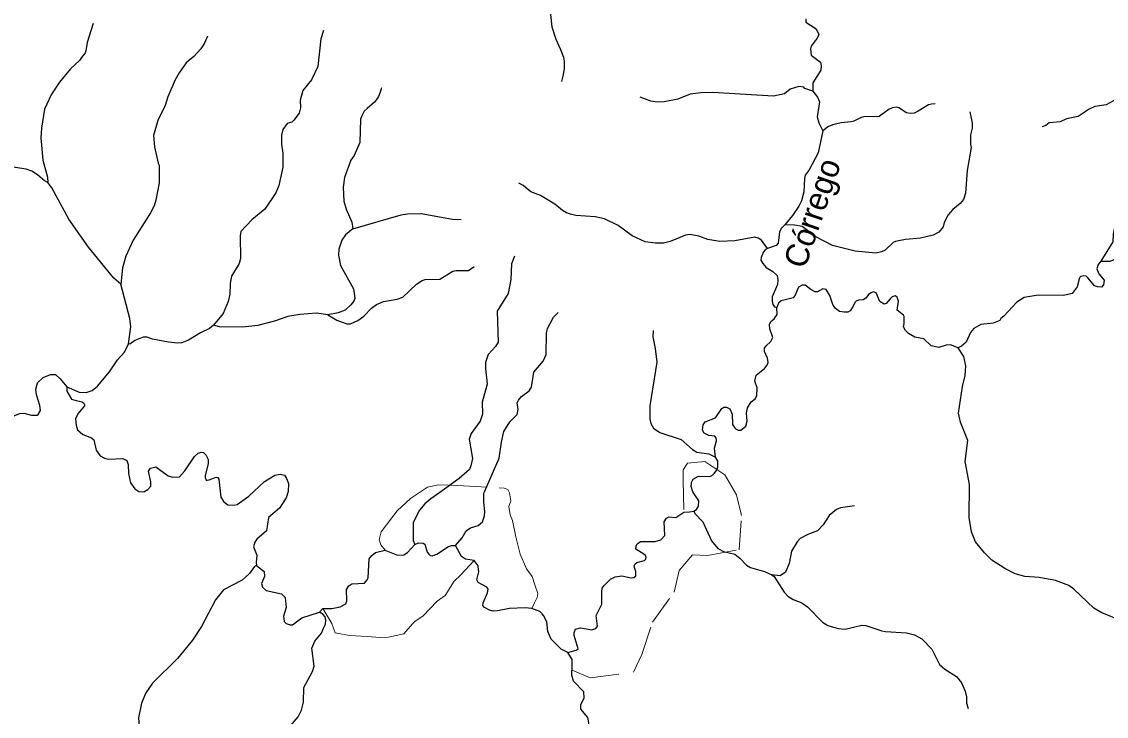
# Model space of a CAD drawing. Extents: x 320.3 to 346.3, y 7455.4 to 7483.3.
# Drawn here: x 336.328 to 340.058, y 7479.449 to 7481.838 of the extents above; entities that cross this region are included whole.
import ezdxf
from ezdxf.enums import TextEntityAlignment as Align

# ---------------------------------------------------------------- set-up
doc = ezdxf.new("R2010")
doc.units = 0
doc.header["$LTSCALE"] = 0.032
doc.linetypes.add('SHORT_DASHED', pattern=[2.7, 1.5, -1.2])
doc.layers.add('21', color=7, linetype='SHORT_DASHED', lineweight=13)
doc.layers.add('7', color=7, linetype='Continuous', lineweight=25)
doc.layers.add('61', color=7, linetype='Continuous')

msp = doc.modelspace()

# ---------------------------------------------------------------- linework, layer by layer
at = {"layer": '21'}
for points in [[(338.2208, 7479.6077), (338.2826, 7479.581), (338.4315, 7479.6011), (338.4601, 7479.6613), (338.4973, 7479.773), (338.5718, 7479.8761), (338.5889, 7479.9506), (338.6347, 7480.005), (338.6863, 7480.0022), (338.7951, 7480.0222), (338.8037, 7480.1397), (338.7865, 7480.2113), (338.7464, 7480.28), (338.6777, 7480.3259), (338.6176, 7480.3201), (338.6032, 7480.2972), (338.6032, 7480.26), (338.6056, 7480.1509)], [(337.6195, 7480.1558), (337.6651, 7480.1978), (337.7243, 7480.2377)], [(337.7243, 7480.2377), (337.7616, 7480.2452), (337.8278, 7480.2425), (337.9697, 7480.2344)], [(337.9697, 7480.2344), (337.9869, 7480.2335), (337.9994, 7480.2291), (338.0057, 7480.218)], [(338.0057, 7480.218), (338.0101, 7480.1906), (338.0038, 7480.171), (338.0083, 7480.1423), (338.0164, 7480.1225)], [(337.5777, 7480.0204), (337.5629, 7480.039), (337.558, 7480.0562), (337.5639, 7480.0837), (337.6195, 7480.1558)], [(338.0164, 7480.1225), (338.028, 7480.0663), (338.0423, 7480.0073), (338.0646, 7479.956)], [(337.8159, 7479.9135), (337.8367, 7479.9349), (337.8838, 7479.9851)], [(338.0646, 7479.956), (338.0834, 7479.9295), (338.0923, 7479.9012), (338.1032, 7479.8718), (338.1005, 7479.858)], [(337.757, 7479.8447), (337.7849, 7479.8652), (337.8159, 7479.9135)], [(337.6817, 7479.7759), (337.708, 7479.7936), (337.757, 7479.8447)], [(338.1005, 7479.858), (338.0914, 7479.8392), (338.0826, 7479.8198)], [(337.3643, 7479.8195), (337.3951, 7479.7685), (337.4068, 7479.7366)], [(337.6424, 7479.7333), (337.6714, 7479.7659), (337.6817, 7479.7759)], [(337.4068, 7479.7366), (337.4551, 7479.7266), (337.5167, 7479.7239), (337.5614, 7479.7203), (337.59, 7479.7212), (337.6424, 7479.7333)]]:
    msp.add_lwpolyline(points, dxfattribs=at)
at = {"layer": '7'}
for points in [[(338.181, 7482.0499), (338.1843, 7482.0255), (338.1824, 7482.005), (338.1498, 7481.8941), (338.1468, 7481.8625), (338.1513, 7481.8197), (338.1648, 7481.778), (338.1813, 7481.7427), (338.1908, 7481.7156), (338.1933, 7481.7017), (338.1934, 7481.676), (338.1887, 7481.651), (338.1839, 7481.632)], [(339.0241, 7481.8479), (339.0251, 7481.8366), (339.0565, 7481.8161), (339.064, 7481.807), (339.0688, 7481.7943), (339.0639, 7481.7814), (339.0429, 7481.7539), (339.0406, 7481.7446), (339.0428, 7481.7231), (339.0745, 7481.6987), (339.0772, 7481.6858), (339.0763, 7481.6715), (339.0482, 7481.6272), (339.0486, 7481.5993)], [(336.5741, 7481.8315), (336.554, 7481.766), (336.5487, 7481.7379), (336.5463, 7481.7306), (336.543, 7481.7261), (336.5342, 7481.7146), (336.5275, 7481.705), (336.4959, 7481.6761), (336.458, 7481.6303), (336.4308, 7481.589), (336.407, 7481.5371), (336.3963, 7481.472), (336.3939, 7481.4384), (336.4012, 7481.3621), (336.4173, 7481.3029), (336.4184, 7481.2852)], [(337.3657, 7481.8073), (337.3571, 7481.7787), (337.3469, 7481.6843), (337.3251, 7481.638), (337.2954, 7481.6015), (337.2863, 7481.5685), (337.2871, 7481.5417), (337.2828, 7481.5238), (337.2644, 7481.4993), (337.2569, 7481.4927), (337.2417, 7481.4874), (337.2262, 7481.467), (337.2217, 7481.4475), (337.2216, 7481.4169), (337.2264, 7481.3853), (337.2264, 7481.3379), (337.2128, 7481.2743), (337.2023, 7481.2494), (337.1644, 7481.1927), (337.1203, 7481.1564), (337.0824, 7481.1167), (337.08, 7481.1014), (337.0805, 7481.0234), (337.0759, 7481.0059), (337.0497, 7480.9626), (337.0447, 7480.9381), (337.0442, 7480.901), (337.0388, 7480.8753), (337.0217, 7480.8341), (336.9876, 7480.7949)], [(336.9675, 7481.788), (336.9574, 7481.7641), (336.944, 7481.7447), (336.9198, 7481.7178), (336.8942, 7481.6959), (336.8701, 7481.6625), (336.8556, 7481.6376), (336.8309, 7481.5795), (336.8221, 7481.5499), (336.796, 7481.4978), (336.7812, 7481.4469), (336.7847, 7481.4081), (336.7978, 7481.3509), (336.8016, 7481.3445), (336.8014, 7481.2833), (336.7893, 7481.2246), (336.7835, 7481.2043), (336.7718, 7481.1806), (336.7117, 7481.0863), (336.6863, 7481.0313), (336.6747, 7480.992), (336.669, 7480.9351)], [(339.0486, 7481.5993), (339.0216, 7481.6085), (339.0182, 7481.6126), (339.0002, 7481.6149), (338.9705, 7481.6062), (338.9511, 7481.5903), (338.9133, 7481.5818), (338.7035, 7481.595), (338.6638, 7481.5934), (338.6274, 7481.5889), (338.5845, 7481.5718), (338.538, 7481.5622), (338.5147, 7481.5612), (338.4918, 7481.565), (338.455, 7481.5789)], [(337.5652, 7481.611), (337.5613, 7481.5957), (337.5553, 7481.5812), (337.5486, 7481.5703), (337.5417, 7481.5617), (337.516, 7481.5396), (337.5064, 7481.5308), (337.4978, 7481.514), (337.4937, 7481.5023), (337.4912, 7481.4226), (337.4715, 7481.3775), (337.4603, 7481.362), (337.4389, 7481.3025), (337.4341, 7481.2692), (337.4363, 7481.2212), (337.4441, 7481.1935), (337.463, 7481.1491), (337.467, 7481.1261)], [(339.0486, 7481.5993), (339.0646, 7481.5782), (339.0716, 7481.5619), (339.0634, 7481.5113), (339.0694, 7481.4904), (339.0831, 7481.4628)], [(340.1924, 7481.5821), (340.1671, 7481.6051), (340.1494, 7481.6123), (340.1366, 7481.6112), (340.1185, 7481.5989), (340.0825, 7481.5659), (340.0571, 7481.5519), (340.0187, 7481.5458), (339.999, 7481.5369), (339.9611, 7481.5122), (339.921, 7481.5044), (339.8991, 7481.494), (339.8617, 7481.4896), (339.8499, 7481.4807), (339.8372, 7481.4767)], [(339.4691, 7481.5551), (339.4561, 7481.5543), (339.4467, 7481.552), (339.411, 7481.53), (339.3974, 7481.5232), (339.3831, 7481.5219), (339.3709, 7481.5246), (339.3446, 7481.5418), (339.3349, 7481.5437), (339.322, 7481.5419), (339.3111, 7481.5371), (339.2771, 7481.512), (339.2706, 7481.5108), (339.2373, 7481.5123), (339.2234, 7481.5102), (339.2149, 7481.508), (339.1898, 7481.4963), (339.1787, 7481.4934), (339.1459, 7481.49), (339.1203, 7481.4846), (339.102, 7481.4776), (339.0831, 7481.4628)], [(339.5886, 7481.5274), (339.5965, 7481.4902), (339.5963, 7481.4713), (339.5902, 7481.4487), (339.5902, 7481.4171), (339.593, 7481.405), (339.5796, 7481.3266), (339.5734, 7481.2479), (339.5664, 7481.227), (339.5554, 7481.2128), (339.5303, 7481.1919), (339.5141, 7481.1738), (339.5003, 7481.1473), (339.4965, 7481.1329), (339.4817, 7481.1139), (339.462, 7481.1044), (339.4185, 7481.0931), (339.3675, 7481.089), (339.3326, 7481.0822), (339.3253, 7481.079), (339.2973, 7481.0522), (339.2844, 7481.0464), (339.2652, 7481.0425), (339.1947, 7481.0484), (339.1164, 7481.0679), (339.0584, 7481.0986), (339.0117, 7481.1331), (338.9852, 7481.1384), (338.9523, 7481.1396)], [(339.0831, 7481.4628), (339.0665, 7481.3868), (339.0361, 7481.3287), (339.0223, 7481.31), (339.0201, 7481.2991), (339.018, 7481.2524), (339.01, 7481.2224), (339.0006, 7481.2036), (338.9789, 7481.1717), (338.9523, 7481.1396)], [(336.4184, 7481.2852), (336.4066, 7481.2912), (336.3833, 7481.3118), (336.3631, 7481.3235), (336.3439, 7481.3303), (336.2288, 7481.3479), (336.1977, 7481.3492), (336.0964, 7481.3629), (336.0698, 7481.3616), (336.0444, 7481.3659), (336.0271, 7481.37), (336.01, 7481.3769), (335.9771, 7481.4067)], [(340.1962, 7481.4088), (340.1873, 7481.3925), (340.1856, 7481.3812), (340.1861, 7481.3694), (340.1954, 7481.3406), (340.1917, 7481.3037), (340.1789, 7481.2826), (340.1485, 7481.2558), (340.1328, 7481.2268), (340.1191, 7481.1819), (340.0896, 7481.1486), (340.0812, 7481.1075), (340.0806, 7481.0814), (340.0385, 7481.0149)], [(336.669, 7480.9351), (336.6455, 7480.9556), (336.5581, 7481.0621), (336.4906, 7481.1594), (336.4325, 7481.2669), (336.4184, 7481.2852)], [(338.8932, 7481.0581), (338.8718, 7481.0867), (338.8605, 7481.0936), (338.849, 7481.0967), (338.7803, 7481.0847), (338.7293, 7481.0824), (338.6881, 7481.0884), (338.6569, 7481.1007), (338.6263, 7481.1061), (338.6108, 7481.1035), (338.5585, 7481.082), (338.535, 7481.0767), (338.5076, 7481.0765), (338.4723, 7481.0812), (338.4277, 7481.1018), (338.3789, 7481.1373), (338.3326, 7481.1597), (338.3001, 7481.1664), (338.2338, 7481.1709), (338.2159, 7481.1757), (338.2014, 7481.1809), (338.1884, 7481.1891), (338.1612, 7481.2102), (338.1122, 7481.2408), (338.0789, 7481.2532), (338.0523, 7481.2747), (338.0375, 7481.2828)], [(337.467, 7481.1261), (337.6336, 7481.1743), (337.6555, 7481.1768), (337.7021, 7481.1785), (337.8093, 7481.1589), (337.8396, 7481.1581)], [(338.9523, 7481.1396), (338.9408, 7481.1282), (338.9339, 7481.1151), (338.9298, 7481.0766), (338.9224, 7481.068), (338.8932, 7481.0581)], [(337.467, 7481.1261), (337.4413, 7481.1045), (337.429, 7481.0863), (337.4185, 7481.0555), (337.418, 7481.0345), (337.425, 7480.999), (337.4697, 7480.919), (337.474, 7480.8873), (337.4704, 7480.8771), (337.4606, 7480.8642), (337.441, 7480.8464), (337.4169, 7480.8366), (337.3816, 7480.83)], [(338.8932, 7481.0581), (338.8862, 7481.0551), (338.8794, 7481.046), (338.8704, 7481.0266), (338.8697, 7481.0177), (338.8762, 7481.0064), (338.8887, 7480.9924), (338.9111, 7480.9791), (338.9258, 7480.9655), (338.928, 7480.9503), (338.927, 7480.9345), (338.9083, 7480.8919), (338.9083, 7480.8763), (338.9106, 7480.865), (338.9169, 7480.8578), (338.9253, 7480.8546)], [(338.023, 7481.0318), (338.0128, 7481.005), (338.0107, 7480.9519), (338.0008, 7480.9031), (337.9635, 7480.843), (337.9664, 7480.7364), (337.9576, 7480.7207), (337.9321, 7480.6932), (337.9235, 7480.6659), (337.9226, 7480.645), (337.9286, 7480.5917), (337.9118, 7480.5291), (337.9133, 7480.4881), (337.9052, 7480.4646), (337.8735, 7480.4213), (337.8672, 7480.4022), (337.8779, 7480.3354), (337.8728, 7480.3109), (337.8678, 7480.2982), (337.8329, 7480.2666), (337.7741, 7480.2251), (337.7349, 7480.1975), (337.7142, 7480.18), (337.6963, 7480.1581), (337.6739, 7480.1161), (337.6749, 7480.054), (337.6804, 7480.0405)], [(340.0385, 7481.0149), (340.0705, 7481.0147), (340.1038, 7481.0278), (340.1242, 7481.0255), (340.1328, 7481.0197), (340.1361, 7481.0136), (340.1356, 7480.9964), (340.1275, 7480.9644), (340.1294, 7480.9476), (340.1334, 7480.9408), (340.1456, 7480.9317), (340.1684, 7480.921), (340.1848, 7480.9007), (340.2013, 7480.8866), (340.228, 7480.8847), (340.2589, 7480.8871), (340.29, 7480.8706), (340.3068, 7480.8572), (340.3099, 7480.8526), (340.3085, 7480.8403), (340.2972, 7480.8148), (340.2938, 7480.7996), (340.2953, 7480.7912)], [(337.3816, 7480.83), (337.4116, 7480.8114), (337.4459, 7480.7991), (337.4589, 7480.7988), (337.4846, 7480.8108), (337.5046, 7480.8251), (337.531, 7480.8526), (337.5483, 7480.8652), (337.5724, 7480.8755), (337.6199, 7480.8838), (337.6387, 7480.8911), (337.6864, 7480.9359), (337.7054, 7480.9477), (337.7162, 7480.9512), (337.7662, 7480.9522), (337.8106, 7480.9801), (337.8218, 7480.9826), (337.8651, 7480.9821), (337.8842, 7480.9963)], [(340.0385, 7481.0149), (340.0299, 7481.0028), (340.0253, 7480.9879), (340.0318, 7480.971), (340.0501, 7480.9489), (340.0482, 7480.9333), (340.0407, 7480.9252), (340.0275, 7480.9258), (340.0172, 7480.9297), (339.9957, 7480.9564), (339.9882, 7480.9629), (339.9806, 7480.9643), (339.9703, 7480.962), (339.9651, 7480.9568), (339.9579, 7480.9264), (339.9402, 7480.9034), (339.9101, 7480.8969), (339.8229, 7480.8978), (339.7758, 7480.8891), (339.7497, 7480.8738), (339.7051, 7480.8248), (339.6946, 7480.817), (339.6916, 7480.8099), (339.669, 7480.8009), (339.6261, 7480.7961), (339.6016, 7480.7833), (339.5911, 7480.7688), (339.5759, 7480.7358), (339.5597, 7480.7216), (339.5479, 7480.7169)], [(336.6959, 7480.7296), (336.7034, 7480.7889), (336.7002, 7480.8178), (336.669, 7480.9351)], [(339.5479, 7480.7169), (339.5215, 7480.7269), (339.5076, 7480.7258), (339.4814, 7480.7178), (339.4557, 7480.7229), (339.4298, 7480.7471), (339.399, 7480.7532), (339.3774, 7480.7652), (339.3671, 7480.7757), (339.3603, 7480.7882), (339.3632, 7480.8003), (339.3626, 7480.8238), (339.3599, 7480.829), (339.3382, 7480.8459), (339.3429, 7480.8768), (339.3383, 7480.8901), (339.3319, 7480.8951), (339.3214, 7480.8919), (339.3145, 7480.8848), (339.3008, 7480.8685), (339.2941, 7480.867), (339.2793, 7480.8761), (339.266, 7480.9057), (339.2575, 7480.9094), (339.2491, 7480.9058), (339.2403, 7480.8996), (339.231, 7480.8868), (339.2215, 7480.8816), (339.2061, 7480.8808), (339.1981, 7480.8768), (339.1931, 7480.8721), (339.1873, 7480.8598), (339.1772, 7480.8431), (339.1689, 7480.8386), (339.1562, 7480.8386), (339.1404, 7480.8413), (339.1263, 7480.8516), (339.1175, 7480.865), (339.1069, 7480.8965), (339.094, 7480.9171), (339.0825, 7480.9189), (339.0642, 7480.9092), (339.0567, 7480.9093), (339.042, 7480.9165), (339.0226, 7480.932), (339.0118, 7480.9315), (338.9988, 7480.9251), (338.9884, 7480.8975), (338.9809, 7480.8881), (338.9392, 7480.8776), (338.9309, 7480.8702), (338.9253, 7480.8546)], [(337.3816, 7480.83), (337.3423, 7480.8357), (337.2844, 7480.8311), (337.2432, 7480.8236), (337.1975, 7480.808), (337.1399, 7480.7936), (337.0881, 7480.7872), (337.0084, 7480.7888), (336.9876, 7480.7949)], [(337.8199, 7480.0361), (337.8431, 7480.0627), (337.8562, 7480.0872), (337.8718, 7480.0972), (337.8978, 7480.1049), (337.9126, 7480.1184), (337.9197, 7480.1384), (337.9213, 7480.1531), (337.9169, 7480.1862), (337.9173, 7480.2163), (337.9194, 7480.221), (337.9705, 7480.3375), (337.9777, 7480.3925), (337.9866, 7480.4289), (338.0072, 7480.4623), (338.0318, 7480.4868), (338.0358, 7480.5044), (338.0326, 7480.5275), (338.0367, 7480.536), (338.0465, 7480.5487), (338.0733, 7480.5688), (338.0811, 7480.581), (338.0895, 7480.6323), (338.121, 7480.6705), (338.1315, 7480.6934), (338.1324, 7480.7667), (338.1362, 7480.7832), (338.1566, 7480.8215), (338.1728, 7480.838)], [(338.7135, 7480.3401), (338.7108, 7480.3716), (338.7175, 7480.3969), (338.7164, 7480.4065), (338.7122, 7480.4128), (338.6907, 7480.4151), (338.6745, 7480.4227), (338.6698, 7480.4333), (338.6715, 7480.4518), (338.6781, 7480.4615), (338.7138, 7480.4758), (338.7358, 7480.5077), (338.7429, 7480.5122), (338.7523, 7480.5128), (338.7631, 7480.5061), (338.7709, 7480.4888), (338.7728, 7480.4529), (338.7815, 7480.4394), (338.7922, 7480.4336), (338.8015, 7480.4327), (338.8183, 7480.4474), (338.8229, 7480.4641), (338.821, 7480.4933), (338.8241, 7480.51), (338.8366, 7480.5307), (338.8514, 7480.5426), (338.8556, 7480.5525), (338.8573, 7480.5784), (338.8488, 7480.6019), (338.8536, 7480.6222), (338.882, 7480.6456), (338.8908, 7480.656), (338.8945, 7480.6665), (338.8927, 7480.6804), (338.8828, 7480.7033), (338.8828, 7480.7153), (338.8877, 7480.7236), (338.9044, 7480.7385), (338.9108, 7480.7517), (338.9002, 7480.7814), (338.8999, 7480.7972), (338.9043, 7480.8066), (338.916, 7480.8161), (338.9264, 7480.8314), (338.9253, 7480.8546)], [(336.9876, 7480.7949), (336.9737, 7480.7834), (336.9428, 7480.7683), (336.9025, 7480.743), (336.8786, 7480.734), (336.8637, 7480.7319), (336.8327, 7480.7354), (336.7784, 7480.7459), (336.7598, 7480.7526), (336.7457, 7480.7525), (336.717, 7480.7419), (336.7008, 7480.7295), (336.6959, 7480.7296)], [(338.4993, 7480.7759), (338.498, 7480.7542), (338.507, 7480.7136), (338.5119, 7480.6668), (338.488, 7480.5171), (338.488, 7480.4716), (338.4918, 7480.4559), (338.501, 7480.4403), (338.5223, 7480.4252), (338.5957, 7480.4008), (338.6349, 7480.3665), (338.6502, 7480.3574), (338.6911, 7480.3517), (338.7135, 7480.3401)], [(336.4832, 7480.5824), (336.5263, 7480.5635), (336.5506, 7480.5625), (336.5711, 7480.5697), (336.5894, 7480.5844), (336.6302, 7480.634), (336.6584, 7480.6746), (336.6815, 7480.7012), (336.6959, 7480.7296)], [(340.1098, 7479.7778), (340.0427, 7479.8052), (340.0145, 7479.8209), (339.9455, 7479.887), (339.9286, 7479.8988), (339.8826, 7479.9164), (339.8267, 7479.927), (339.7774, 7479.9301), (339.7446, 7479.939), (339.709, 7479.9576), (339.6637, 7479.9866), (339.639, 7480.011), (339.6077, 7480.0487), (339.5944, 7480.0837), (339.5859, 7480.1327), (339.5868, 7480.2466), (339.5724, 7480.326), (339.5819, 7480.3972), (339.5562, 7480.4606), (339.5493, 7480.4914), (339.5628, 7480.5829), (339.5724, 7480.6207), (339.5751, 7480.655), (339.5683, 7480.6869), (339.5479, 7480.7169)], [(336.1919, 7480.3977), (336.2141, 7480.4039), (336.2471, 7480.4002), (336.2637, 7480.4048), (336.271, 7480.4278), (336.2712, 7480.4533), (336.2831, 7480.4721), (336.3073, 7480.4844), (336.3226, 7480.4905), (336.3354, 7480.4917), (336.3621, 7480.4847), (336.3817, 7480.4843), (336.3856, 7480.4867), (336.3932, 7480.5006), (336.3906, 7480.5184), (336.3789, 7480.5547), (336.3773, 7480.5741), (336.3832, 7480.5964), (336.4028, 7480.6139), (336.4276, 7480.6247), (336.4451, 7480.6242), (336.4612, 7480.6102), (336.4832, 7480.5824)], [(336.4832, 7480.5824), (336.484, 7480.5677), (336.5002, 7480.5404), (336.5156, 7480.535), (336.5368, 7480.5312), (336.5425, 7480.526), (336.5445, 7480.5214), (336.5445, 7480.5174), (336.5211, 7480.4895), (336.514, 7480.4727), (336.5156, 7480.4499), (336.5209, 7480.4348), (336.5384, 7480.4181), (336.5687, 7480.4067), (336.5765, 7480.4002), (336.585, 7480.3649), (336.5988, 7480.3449), (336.6127, 7480.3371), (336.6273, 7480.3336), (336.6765, 7480.3363), (336.6894, 7480.3291), (336.6951, 7480.3152), (336.6956, 7480.2842), (336.703, 7480.2521), (336.7169, 7480.2317), (336.7317, 7480.2222), (336.7484, 7480.2213), (336.7625, 7480.2293), (336.7721, 7480.2405), (336.772, 7480.2558), (336.7647, 7480.2919), (336.7715, 7480.3025), (336.7891, 7480.3073), (336.8319, 7480.2757), (336.8467, 7480.2714), (336.871, 7480.2725), (336.8891, 7480.2929), (336.9224, 7480.3428), (336.9354, 7480.354), (336.946, 7480.3575), (336.9536, 7480.3565), (336.962, 7480.349), (336.9694, 7480.3326), (336.9699, 7480.3172), (336.9595, 7480.2775), (336.9598, 7480.2691), (336.9611, 7480.2644), (336.9625, 7480.2614), (336.966, 7480.2614), (336.9725, 7480.2625), (336.9967, 7480.272), (337.0026, 7480.2703), (337.0066, 7480.2647), (337.0137, 7480.2032), (337.0239, 7480.1866), (337.0374, 7480.1765), (337.0595, 7480.1748), (337.0691, 7480.1775), (337.1097, 7480.2061), (337.1637, 7480.2563), (337.1993, 7480.279), (337.2168, 7480.2814), (337.2318, 7480.2784), (337.2395, 7480.267), (337.2455, 7480.2499), (337.2442, 7480.2229), (337.2375, 7480.201), (337.215, 7480.165), (337.1768, 7480.1333), (337.1696, 7480.0867), (337.1372, 7480.0588), (337.13, 7480.0486), (337.1259, 7480.032), (337.1365, 7480.0039), (337.1343, 7479.9784), (337.1363, 7479.9682)], [(338.6393, 7480.1545), (338.6488, 7480.1608), (338.6557, 7480.1715), (338.6568, 7480.1904), (338.6363, 7480.221), (338.6301, 7480.2393), (338.631, 7480.2538), (338.6372, 7480.2651), (338.6556, 7480.2747), (338.6941, 7480.2739), (338.704, 7480.278), (338.7092, 7480.2846), (338.717, 7480.2946), (338.7215, 7480.3077), (338.7221, 7480.3266), (338.7135, 7480.3401)], [(339.192, 7480.1734), (339.1434, 7480.1659), (339.1303, 7480.1604), (339.1052, 7480.1398), (339.0839, 7480.1076), (339.065, 7480.0866), (339.0316, 7480.0749), (339.0053, 7480.0603), (338.9951, 7480.0493), (338.9753, 7480.017), (338.9671, 7479.9744), (338.9552, 7479.9445), (338.9362, 7479.9325), (338.9072, 7479.9352)], [(338.2066, 7479.6685), (338.2344, 7479.6763), (338.2414, 7479.6817), (338.2279, 7479.727), (338.2275, 7479.7377), (338.233, 7479.7489), (338.2495, 7479.7538), (338.2889, 7479.7471), (338.302, 7479.7514), (338.3086, 7479.7591), (338.3036, 7479.7963), (338.3234, 7479.8352), (338.3227, 7479.8784), (338.3242, 7479.8901), (338.3307, 7479.8992), (338.3529, 7479.9212), (338.3689, 7479.9293), (338.3924, 7479.9325), (338.4236, 7479.9256), (338.433, 7479.9268), (338.4406, 7479.9329), (338.4405, 7479.9473), (338.4352, 7479.9615), (338.4346, 7479.967), (338.4374, 7479.9733), (338.4435, 7479.9778), (338.4698, 7479.9846), (338.4748, 7479.9897), (338.476, 7479.9965), (338.4728, 7480.0021), (338.468, 7480.0064), (338.4404, 7480.0243), (338.4407, 7480.0339), (338.4449, 7480.0419), (338.451, 7480.047), (338.4561, 7480.0507), (338.465, 7480.0503), (338.5064, 7480.0501), (338.5263, 7480.0562), (338.5402, 7480.0715), (338.5379, 7480.1186), (338.5453, 7480.1304), (338.553, 7480.1349), (338.5778, 7480.1335), (338.6056, 7480.1509), (338.6247, 7480.1529), (338.6393, 7480.1545)], [(338.6393, 7480.1545), (338.6425, 7480.1465), (338.6699, 7480.1176), (338.7007, 7480.0525), (338.7218, 7480.0265), (338.7244, 7480.025), (338.741, 7480.0157), (338.7803, 7480.0066), (338.7977, 7479.9933), (338.8209, 7479.9692), (338.8345, 7479.9608), (338.882, 7479.947), (338.9072, 7479.9352)], [(337.3522, 7479.8072), (337.3643, 7479.8195), (337.3947, 7479.8203), (337.4235, 7479.8253), (337.4424, 7479.8362), (337.4468, 7479.8466), (337.4455, 7479.8857), (337.4538, 7479.8984), (337.4641, 7479.9044), (337.5073, 7479.907), (337.5166, 7479.9181), (337.5193, 7479.9259), (337.5228, 7479.9904), (337.5318, 7480.0026), (337.5449, 7480.0127), (337.5777, 7480.0204), (337.5806, 7480.0193), (337.6211, 7480.0038), (337.6422, 7480.0049), (337.6545, 7480.0128), (337.6804, 7480.0405)], [(337.6804, 7480.0405), (337.6929, 7480.0456), (337.7086, 7480.0446), (337.7144, 7480.0407), (337.7225, 7480.0142), (337.7281, 7480.0069), (337.7333, 7480.0025), (337.7403, 7480.0013), (337.7563, 7480.0068), (337.7959, 7480.0335), (337.8064, 7480.0369), (337.8199, 7480.0361)], [(338.2066, 7479.6685), (338.183, 7479.6805), (338.149, 7479.7151), (338.1377, 7479.7411), (338.1341, 7479.7743), (338.1222, 7479.7958), (338.1175, 7479.8012), (338.1096, 7479.8102), (338.0826, 7479.8198), (338.0593, 7479.8224), (338.0057, 7479.8198), (337.9646, 7479.8115), (337.9496, 7479.8113), (337.9371, 7479.8141), (337.9201, 7479.8231), (337.9143, 7479.8305), (337.915, 7479.8394), (337.9306, 7479.8733), (337.9325, 7479.887), (337.9277, 7479.8939), (337.8978, 7479.9093), (337.8934, 7479.919), (337.8997, 7479.9463), (337.8985, 7479.9632), (337.8982, 7479.9668), (337.8838, 7479.9851), (337.8539, 7479.99), (337.8401, 7479.9985), (337.8199, 7480.0361)], [(337.1363, 7479.9682), (337.129, 7479.9646), (337.1121, 7479.9406), (337.0863, 7479.9173), (337.0224, 7479.8842), (336.9949, 7479.8495), (336.947, 7479.7579), (336.9159, 7479.7114), (336.8647, 7479.6482), (336.7785, 7479.5637), (336.7551, 7479.5304), (336.7402, 7479.4945), (336.7297, 7479.4444), (336.7387, 7479.3229), (336.7324, 7479.2683), (336.7245, 7479.2393)], [(337.1363, 7479.9682), (337.1618, 7479.9471), (337.1635, 7479.9303), (337.1526, 7479.9056), (337.1569, 7479.8934), (337.1695, 7479.8818), (337.2212, 7479.87), (337.2342, 7479.8579), (337.2382, 7479.824), (337.2281, 7479.794), (337.231, 7479.7751), (337.2373, 7479.7687), (337.2512, 7479.7635), (337.2596, 7479.7639), (337.2921, 7479.7875), (337.3522, 7479.8072)], [(338.9072, 7479.9352), (338.9153, 7479.9295), (338.95, 7479.8764), (338.9631, 7479.8627), (338.9813, 7479.8515), (339.0109, 7479.8391), (339.0307, 7479.8259), (339.0821, 7479.7731), (339.0997, 7479.762), (339.1354, 7479.7508), (339.1599, 7479.7488), (339.217, 7479.7625), (339.2314, 7479.762), (339.2862, 7479.7429), (339.2983, 7479.7407), (339.3709, 7479.7364), (339.3981, 7479.7289), (339.4231, 7479.7152), (339.4573, 7479.6799), (339.484, 7479.6274), (339.5029, 7479.6115), (339.5429, 7479.5864), (339.5595, 7479.5639), (339.5725, 7479.5359), (339.577, 7479.5168), (339.5775, 7479.4944), (339.583, 7479.4758)], [(337.2067, 7479.1227), (337.2047, 7479.1664), (337.2075, 7479.1946), (337.2165, 7479.2243), (337.2318, 7479.2537), (337.2481, 7479.2994), (337.2505, 7479.3403), (337.2455, 7479.3999), (337.2524, 7479.4169), (337.2793, 7479.4475), (337.291, 7479.4703), (337.2969, 7479.4976), (337.299, 7479.5487), (337.3286, 7479.6038), (337.334, 7479.6216), (337.3261, 7479.6832), (337.336, 7479.7081), (337.3588, 7479.7355), (337.3661, 7479.7519), (337.3726, 7479.7663), (337.3742, 7479.7797), (337.3717, 7479.7915), (337.3637, 7479.8008), (337.3522, 7479.8072)], [(338.2758, 7479.4121), (338.2787, 7479.4273), (338.2749, 7479.4448), (338.2506, 7479.4743), (338.2507, 7479.489), (338.2622, 7479.5123), (338.2608, 7479.5331), (338.2257, 7479.5704), (338.2205, 7479.5904), (338.2211, 7479.625), (338.2215, 7479.645), (338.2066, 7479.6685)]]:
    msp.add_lwpolyline(points, dxfattribs=at)

# ---------------------------------------------------------------- texts
at = {"layer": '61'}
msp.add_text('Córrego', height=0.08, rotation=71.13, dxfattribs=at).set_placement((339.0841, 7481.1673), align=Align.CENTER)

doc.saveas('drawing.dxf')
